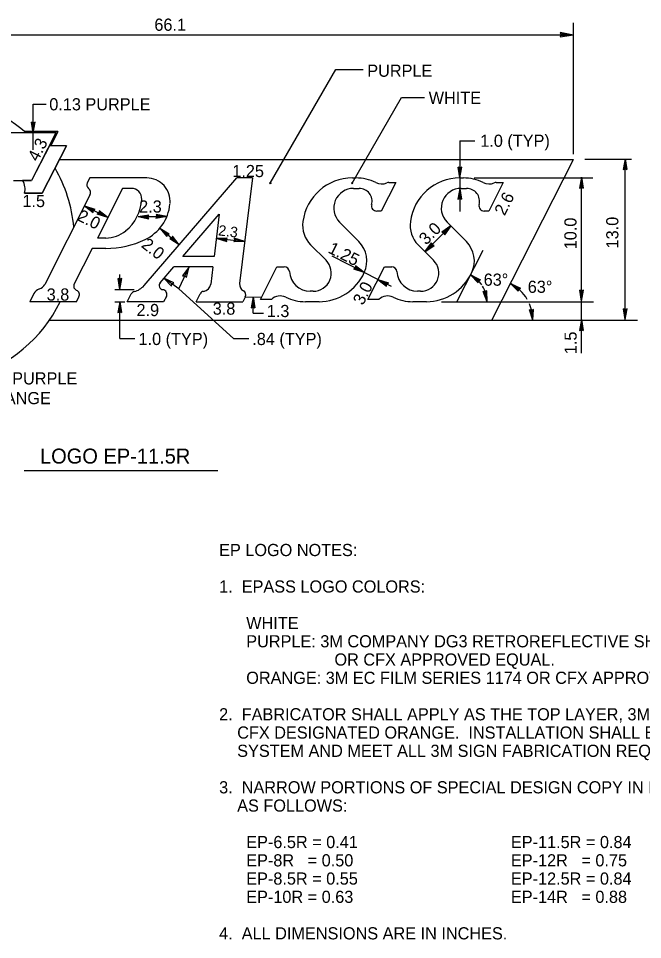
# Model space of a CAD drawing. Extents: x 10268197 to 10269179, y 2141503 to 2142677.
# Drawn here: x 10268671.1 to 10268707, y 2142084.7 to 2142137.7 of the extents above; entities that cross this region are included whole.
import ezdxf

# ---------------------------------------------------------------- set-up
doc = ezdxf.new("R2010")
doc.units = 0
for name, color, linetype in [('1', 7, 'Continuous'), ('20', 7, 'Continuous'), ('21', 7, 'Continuous'), ('3', 7, 'Continuous'), ('52', 7, 'Continuous'), ('Default', 7, 'Continuous'), ('TextNotes', 7, 'Continuous')]:
    doc.layers.add(name, color=color, linetype=linetype)

msp = doc.modelspace()

# ---------------------------------------------------------------- linework, layer by layer
at = {"layer": '1'}
for p, q in [((10268673.238, 2142131.13), (10268664.613, 2142131.13)), ((10268673.362, 2142131.206), (10268671.443, 2142131.206)), ((10268673.238, 2142131.13), (10268671.844, 2142128.396)), ((10268673.362, 2142131.206), (10268672.95, 2142130.4)), ((10268672.865, 2142130.4), (10268671.844, 2142128.396)), ((10268672.456, 2142127.664), (10268673.85, 2142130.4)), ((10268673.85, 2142130.4), (10268672.456, 2142127.664)), ((10268673.85, 2142130.4), (10268672.865, 2142130.4)), ((10268673.85, 2142130.4), (10268672.865, 2142130.4)), ((10268673.447, 2142129.611), (10268703.052, 2142129.611)), ((10268698.337, 2142120.356), (10268703.052, 2142129.611)), ((10268675.19, 2142128.543), (10268675.048, 2142128.262)), ((10268678.475, 2142128.543), (10268675.19, 2142128.543)), ((10268678.316, 2142122.348), (10268683.66, 2142128.543)), ((10268684.559, 2142128.543), (10268683.66, 2142128.543)), ((10268684.559, 2142128.543), (10268683.819, 2142122.472)), ((10268690.317, 2142128.543), (10268690.515, 2142128.543)), ((10268696.504, 2142128.543), (10268696.703, 2142128.543)), ((10268670.804, 2142128.395), (10268671.844, 2142128.396)), ((10268671.844, 2142128.396), (10268671.325, 2142128.396)), ((10268677.076, 2142127.945), (10268675.632, 2142125.089)), ((10268677.586, 2142127.945), (10268677.076, 2142127.945)), ((10268690.38, 2142127.945), (10268690.699, 2142127.945)), ((10268692.806, 2142128.28), (10268691.974, 2142126.635)), ((10268692.414, 2142128.28), (10268692.806, 2142128.28)), ((10268696.567, 2142127.945), (10268696.887, 2142127.945)), ((10268698.994, 2142128.28), (10268698.162, 2142126.635)), ((10268698.601, 2142128.28), (10268698.994, 2142128.28)), ((10268672.456, 2142127.664), (10268671.433, 2142127.665)), ((10268671.433, 2142127.665), (10268672.456, 2142127.664)), ((10268675.199, 2142127.547), (10268672.607, 2142122.422)), ((10268680.553, 2142124.025), (10268682.646, 2142126.451)), ((10268682.646, 2142126.451), (10268682.351, 2142124.025)), ((10268691.974, 2142126.635), (10268691.713, 2142126.635)), ((10268698.162, 2142126.635), (10268697.9, 2142126.635)), ((10268689.573, 2142126.007), (10268690.687, 2142124.885)), ((10268695.761, 2142126.007), (10268696.875, 2142124.885)), ((10268676.12, 2142125.089), (10268675.632, 2142125.089)), ((10268675.329, 2142124.491), (10268674.296, 2142122.446)), ((10268676.12, 2142124.491), (10268675.329, 2142124.491)), ((10268688.796, 2142123.807), (10268687.91, 2142124.701)), ((10268694.984, 2142123.807), (10268694.097, 2142124.701)), ((10268682.351, 2142124.025), (10268680.553, 2142124.025)), ((10268679.245, 2142122.511), (10268680.037, 2142123.428)), ((10268682.278, 2142123.428), (10268680.037, 2142123.428)), ((10268682.278, 2142123.428), (10268682.158, 2142122.436)), ((10268685.018, 2142121.555), (10268685.968, 2142123.436)), ((10268685.968, 2142123.436), (10268686.389, 2142123.436)), ((10268691.206, 2142121.556), (10268692.157, 2142123.436)), ((10268692.157, 2142123.436), (10268692.577, 2142123.435)), ((10268671.97, 2142121.889), (10268671.736, 2142121.423)), ((10268674.428, 2142121.424), (10268674.57, 2142121.706)), ((10268677.353, 2142121.424), (10268677.58, 2142121.875)), ((10268679.601, 2142121.729), (10268679.446, 2142121.423)), ((10268681.317, 2142121.423), (10268681.546, 2142121.874)), ((10268684.147, 2142121.695), (10268684.009, 2142121.423)), ((10268685.654, 2142121.555), (10268685.018, 2142121.555)), ((10268688.053, 2142122.023), (10268687.882, 2142122.023)), ((10268691.841, 2142121.555), (10268691.206, 2142121.556)), ((10268694.241, 2142122.023), (10268694.07, 2142122.023)), ((10268674.428, 2142121.424), (10268671.736, 2142121.423)), ((10268679.446, 2142121.423), (10268677.353, 2142121.424)), ((10268681.317, 2142121.423), (10268684.009, 2142121.423)), ((10268688.392, 2142121.423), (10268687.604, 2142121.424)), ((10268694.579, 2142121.423), (10268693.792, 2142121.424)), ((10268672.864, 2142120.356), (10268698.337, 2142120.356))]:
    msp.add_line(p, q, dxfattribs=at)
for centre, radius, start, end in [((10268666.115, 2142124.99), 8.187, 48.5904, 218.8792), ((10268666.115, 2142124.99), 8.187, 5.051, 30.1953), ((10268678.474, 2142127.197), 1.346, 354.6609, 90), ((10268670.592, 2142127.914), 0.877, 343.4611, 33.2756), ((10268670.592, 2142127.914), 0.877, 343.4611, 33.2756), ((10268677.586, 2142127.347), 0.598, 356.6133, 90), ((10268690.38, 2142126.808), 1.137, 90, 224.7881), ((10268690.699, 2142127.197), 0.748, 345.4379, 90), ((10268696.568, 2142126.808), 1.137, 90, 224.7881), ((10268696.887, 2142127.197), 0.748, 345.4379, 90), ((10268675.645, 2142127.462), 2.542, 309.3947, 356.6133), ((10268677.282, 2142127.297), 2.542, 295.579, 354.2619), ((10268691.713, 2142126.934), 0.299, 165.4379, 270), ((10268697.9, 2142126.934), 0.299, 165.4379, 270), ((10268676.12, 2142126.884), 1.795, 270, 309.3947), ((10268676.12, 2142129.725), 5.235, 270, 295.579), ((10268688.053, 2142123.069), 1.047, 270, 44.7784), ((10268694.241, 2142123.069), 1.047, 270, 44.7784), ((10268686.389, 2142123.136), 0.299, 3.1643, 90), ((10268687.882, 2142123.219), 1.196, 183.1643, 270), ((10268692.576, 2142123.136), 0.299, 3.1643, 90), ((10268694.07, 2142123.219), 1.196, 183.1643, 270), ((10268674.536, 2142122.325), 0.269, 153.1708, 247.5682), ((10268674.33, 2142121.827), 0.269, 333.1431, 67.5682), ((10268679.427, 2142122.355), 0.239, 139.1995, 262.5416), ((10268679.361, 2142121.85), 0.269, 333.166, 82.5416), ((10268681.682, 2142122.494), 0.479, 277.9506, 353.082), ((10268684.235, 2142122.421), 0.419, 173.0593, 241.464), ((10268681.786, 2142121.753), 0.269, 97.9506, 153.1923), ((10268683.906, 2142121.817), 0.269, 333.284, 61.464), ((10268666.115, 2142124.99), 8.187, 237.0648, 334.1734)]:
    msp.add_arc(centre, radius, start, end, dxfattribs=at)
for centre, major_axis, start_param, end_param in [((10268690.316, 2142125.643), (0, 2.9), 0, 1.436562), ((10268690.515, 2142125.907), (0, 2.637), 5.830963, 6.283185), ((10268696.503, 2142125.643), (0, 2.9), 0, 1.436562), ((10268696.702, 2142125.907), (0, 2.637), 5.830963, 6.283185), ((10268675.281, 2142128.142), (0, -0.264), 4.240773, 5.605302), ((10268674.919, 2142127.69), (0, -0.316), 1.099604, 2.46371), ((10268692.001, 2142128.99), (0, 0.791), 2.68937, 3.526171), ((10268692.414, 2142127.963), (0, 0.316), 0, 0.384579), ((10268698.189, 2142128.99), (0, 0.791), 2.68937, 3.526171), ((10268698.601, 2142127.963), (0, 0.316), 0, 0.384579), ((10268689.019, 2142125.819), (0, 1.582), 1.436562, 2.356194), ((10268695.207, 2142125.819), (0, 1.582), 1.436562, 2.356194), ((10268689.577, 2142123.766), (0, -1.582), 1.133591, 2.356194), ((10268695.765, 2142123.766), (0, -1.582), 1.133591, 2.356194), ((10268688.392, 2142124.325), (0, -2.9), 0, 1.133591), ((10268694.579, 2142124.325), (0, -2.9), 0, 1.133591), ((10268672.437, 2142121.65), (0, -0.527), 3.428379, 4.240701), ((10268672.141, 2142122.661), (0, -0.527), 0.286787, 1.099486), ((10268677.526, 2142123.042), (0, -1.055), 0.22194, 0.855152), ((10268677.814, 2142121.755), (0, -0.264), 3.363532, 4.241567), ((10268686.155, 2142121.018), (0, -0.738), 2.69443, 3.895387), ((10268687.604, 2142124.061), (0, -2.637), 5.836023, 6.283185), ((10268692.343, 2142121.018), (0, -0.738), 2.69443, 3.895387), ((10268693.791, 2142124.061), (0, -2.637), 5.836023, 6.283185)]:
    msp.add_ellipse(centre, major_axis=major_axis, ratio=0.992614, start_param=start_param, end_param=end_param, dxfattribs=at)
at = {"layer": '20'}
for p, q in [((10268703.052, 2142130.323), (10268703.052, 2142137.473)), ((10268703.052, 2142136.761), (10268656.015, 2142136.761)), ((10268685.583, 2142128.242), (10268689.354, 2142134.775)), ((10268689.354, 2142134.775), (10268690.943, 2142134.775)), ((10268671.928, 2142131.206), (10268671.927, 2142132.788)), ((10268671.927, 2142132.788), (10268672.677, 2142132.788)), ((10268690.299, 2142128.242), (10268693.141, 2142133.164)), ((10268693.141, 2142133.164), (10268694.46, 2142133.164)), ((10268671.927, 2142130.17), (10268671.928, 2142131.13)), ((10268696.504, 2142130.673), (10268696.504, 2142128.543)), ((10268696.504, 2142130.673), (10268697.362, 2142130.673)), ((10268703.052, 2142129.918), (10268703.052, 2142130.323)), ((10268706.383, 2142129.611), (10268703.691, 2142129.611)), ((10268706.02, 2142120.394), (10268706.021, 2142129.65)), ((10268696.504, 2142128.543), (10268696.504, 2142127.943)), ((10268697.332, 2142128.543), (10268704.156, 2142128.543)), ((10268703.505, 2142121.462), (10268703.505, 2142128.582)), ((10268696.504, 2142127.943), (10268696.503, 2142126.611)), ((10268674.889, 2142126.934), (10268676.223, 2142126.259)), ((10268677.97, 2142126.319), (10268679.629, 2142126.319)), ((10268694.493, 2142124.301), (10268695.986, 2142125.782)), ((10268680.344, 2142124.7), (10268679.229, 2142125.662)), ((10268682.479, 2142125.082), (10268684.112, 2142124.884)), ((10268696.334, 2142121.424), (10268697.843, 2142124.385)), ((10268691, 2142123.096), (10268689.14, 2142124.036)), ((10268680.316, 2142122.159), (10268680.913, 2142123.436)), ((10268676.924, 2142122.136), (10268676.924, 2142122.994)), ((10268680.316, 2142122.159), (10268679.447, 2142122.776)), ((10268691.785, 2142122.699), (10268691, 2142123.096)), ((10268692.569, 2142122.302), (10268691.784, 2142122.699)), ((10268676.642, 2142122.136), (10268677.74, 2142122.136)), ((10268683.473, 2142119.313), (10268680.316, 2142122.159)), ((10268684.147, 2142121.695), (10268685.089, 2142121.696)), ((10268684.603, 2142120.767), (10268684.603, 2142121.696)), ((10268676.642, 2142121.424), (10268677.206, 2142121.424)), ((10268676.924, 2142119.313), (10268676.924, 2142121.424)), ((10268695.451, 2142121.424), (10268698.881, 2142121.424)), ((10268698.881, 2142121.424), (10268704.195, 2142121.424)), ((10268703.505, 2142120.395), (10268703.505, 2142121.462)), ((10268684.603, 2142120.767), (10268685.186, 2142120.766)), ((10268698.337, 2142120.356), (10268706.724, 2142120.356)), ((10268703.505, 2142118.468), (10268703.505, 2142120.395)), ((10268676.924, 2142119.313), (10268677.796, 2142119.313)), ((10268683.473, 2142119.313), (10268684.345, 2142119.313))]:
    msp.add_line(p, q, dxfattribs=at)
for centre in [(10268685.583, 2142128.242), (10268690.299, 2142128.242)]:
    msp.add_circle(centre, 0.0356, dxfattribs=at)
for centre, radius, start, end in [((10268696.334, 2142121.424), 1.73, 33.9529, 63.0014), ((10268696.334, 2142121.424), 1.73, 0, 31.4593), ((10268698.337, 2142120.356), 2.37, 30.3328, 63.0012), ((10268698.337, 2142120.356), 2.37, 360, 23.4794)]:
    msp.add_arc(centre, radius, start, end, dxfattribs=at)
at = {"layer": '21'}
for p, q in [((10268703.052, 2142136.761), (10268702.278, 2142136.912)), ((10268702.278, 2142136.912), (10268702.335, 2142136.774)), ((10268702.335, 2142136.774), (10268702.273, 2142136.638)), ((10268703.052, 2142136.761), (10268702.273, 2142136.638)), ((10268703.052, 2142136.761), (10268702.306, 2142136.709)), ((10268703.052, 2142136.761), (10268702.308, 2142136.839)), ((10268671.928, 2142131.13), (10268671.829, 2142131.754)), ((10268671.937, 2142131.704), (10268671.829, 2142131.754)), ((10268671.928, 2142131.13), (10268671.886, 2142131.727)), ((10268671.928, 2142131.13), (10268672.048, 2142131.75)), ((10268671.928, 2142131.13), (10268671.99, 2142131.726)), ((10268672.048, 2142131.75), (10268671.937, 2142131.704)), ((10268706.021, 2142129.65), (10268705.9, 2142129.03)), ((10268706.021, 2142129.65), (10268705.958, 2142129.054)), ((10268706.021, 2142129.65), (10268706.12, 2142129.026)), ((10268706.021, 2142129.65), (10268706.062, 2142129.052)), ((10268696.504, 2142128.543), (10268696.405, 2142129.167)), ((10268696.513, 2142129.118), (10268696.405, 2142129.167)), ((10268696.504, 2142128.543), (10268696.462, 2142129.141)), ((10268696.504, 2142128.543), (10268696.624, 2142129.163)), ((10268696.504, 2142128.543), (10268696.566, 2142129.139)), ((10268696.624, 2142129.163), (10268696.513, 2142129.118)), ((10268705.9, 2142129.03), (10268706.011, 2142129.075)), ((10268706.011, 2142129.075), (10268706.12, 2142129.026)), ((10268703.505, 2142128.582), (10268703.385, 2142127.962)), ((10268703.505, 2142128.582), (10268703.443, 2142127.986)), ((10268703.505, 2142128.582), (10268703.604, 2142127.958)), ((10268703.505, 2142128.582), (10268703.547, 2142127.985)), ((10268696.504, 2142127.943), (10268696.383, 2142127.323)), ((10268696.504, 2142127.943), (10268696.441, 2142127.347)), ((10268696.504, 2142127.943), (10268696.602, 2142127.32)), ((10268696.504, 2142127.943), (10268696.545, 2142127.346)), ((10268703.385, 2142127.962), (10268703.495, 2142128.007)), ((10268703.495, 2142128.007), (10268703.604, 2142127.958)), ((10268696.383, 2142127.323), (10268696.494, 2142127.369)), ((10268696.494, 2142127.369), (10268696.602, 2142127.32)), ((10268674.889, 2142126.934), (10268675.49, 2142126.741)), ((10268674.889, 2142126.934), (10268675.388, 2142126.547)), ((10268674.889, 2142126.934), (10268675.393, 2142126.61)), ((10268674.889, 2142126.934), (10268675.441, 2142126.702)), ((10268675.388, 2142126.547), (10268675.397, 2142126.666)), ((10268675.397, 2142126.666), (10268675.49, 2142126.741)), ((10268675.715, 2142126.527), (10268675.622, 2142126.452)), ((10268676.223, 2142126.259), (10268675.622, 2142126.452)), ((10268676.223, 2142126.259), (10268675.672, 2142126.491)), ((10268675.725, 2142126.646), (10268675.715, 2142126.527)), ((10268676.223, 2142126.259), (10268675.72, 2142126.583)), ((10268676.223, 2142126.259), (10268675.725, 2142126.646)), ((10268677.97, 2142126.319), (10268678.594, 2142126.418)), ((10268677.97, 2142126.319), (10268678.567, 2142126.361)), ((10268677.97, 2142126.319), (10268678.59, 2142126.199)), ((10268677.97, 2142126.319), (10268678.566, 2142126.257)), ((10268678.544, 2142126.309), (10268678.594, 2142126.418)), ((10268678.59, 2142126.199), (10268678.544, 2142126.309)), ((10268679.055, 2142126.329), (10268679.005, 2142126.22)), ((10268679.629, 2142126.319), (10268679.005, 2142126.22)), ((10268679.629, 2142126.319), (10268679.009, 2142126.439)), ((10268679.009, 2142126.439), (10268679.055, 2142126.329)), ((10268679.629, 2142126.319), (10268679.031, 2142126.277)), ((10268679.629, 2142126.319), (10268679.033, 2142126.381)), ((10268695.986, 2142125.782), (10268695.461, 2142125.431)), ((10268695.986, 2142125.782), (10268695.518, 2142125.406)), ((10268695.986, 2142125.782), (10268695.591, 2142125.332)), ((10268695.986, 2142125.782), (10268695.612, 2142125.272)), ((10268679.229, 2142125.662), (10268679.766, 2142125.329)), ((10268679.229, 2142125.662), (10268679.62, 2142125.166)), ((10268679.229, 2142125.662), (10268679.64, 2142125.226)), ((10268679.229, 2142125.662), (10268679.709, 2142125.303)), ((10268679.62, 2142125.166), (10268679.658, 2142125.279)), ((10268679.658, 2142125.279), (10268679.766, 2142125.329)), ((10268695.461, 2142125.431), (10268695.571, 2142125.385)), ((10268695.571, 2142125.385), (10268695.612, 2142125.272)), ((10268679.916, 2142125.083), (10268679.807, 2142125.032)), ((10268680.344, 2142124.7), (10268679.807, 2142125.032)), ((10268680.344, 2142124.7), (10268679.865, 2142125.058)), ((10268679.953, 2142125.196), (10268679.916, 2142125.083)), ((10268680.344, 2142124.7), (10268679.934, 2142125.136)), ((10268680.344, 2142124.7), (10268679.953, 2142125.196)), ((10268682.479, 2142125.082), (10268683.111, 2142125.105)), ((10268682.479, 2142125.082), (10268683.08, 2142124.888)), ((10268682.479, 2142125.082), (10268683.063, 2142124.948)), ((10268682.479, 2142125.082), (10268683.077, 2142125.052)), ((10268683.048, 2142125.003), (10268683.111, 2142125.105)), ((10268683.08, 2142124.888), (10268683.048, 2142125.003)), ((10268683.543, 2142124.963), (10268683.481, 2142124.861)), ((10268684.112, 2142124.884), (10268683.481, 2142124.861)), ((10268684.112, 2142124.884), (10268683.511, 2142125.078)), ((10268683.511, 2142125.078), (10268683.543, 2142124.963)), ((10268684.112, 2142124.884), (10268683.514, 2142124.914)), ((10268684.112, 2142124.884), (10268683.528, 2142125.017)), ((10268694.493, 2142124.301), (10268694.866, 2142124.811)), ((10268694.493, 2142124.301), (10268694.887, 2142124.751)), ((10268694.907, 2142124.699), (10268694.866, 2142124.811)), ((10268694.493, 2142124.301), (10268694.96, 2142124.677)), ((10268694.493, 2142124.301), (10268695.018, 2142124.652)), ((10268695.018, 2142124.652), (10268694.907, 2142124.699)), ((10268690.491, 2142123.364), (10268690.398, 2142123.289)), ((10268691, 2142123.096), (10268690.398, 2142123.289)), ((10268691, 2142123.096), (10268690.447, 2142123.328)), ((10268690.5, 2142123.483), (10268690.491, 2142123.364)), ((10268691, 2142123.096), (10268690.496, 2142123.421)), ((10268691, 2142123.096), (10268690.5, 2142123.483)), ((10268676.924, 2142122.136), (10268676.825, 2142122.759)), ((10268676.934, 2142122.71), (10268676.825, 2142122.759)), ((10268676.924, 2142122.136), (10268676.882, 2142122.733)), ((10268676.924, 2142122.136), (10268677.044, 2142122.755)), ((10268676.924, 2142122.136), (10268676.986, 2142122.732)), ((10268677.044, 2142122.755), (10268676.934, 2142122.71)), ((10268691.784, 2142122.699), (10268692.386, 2142122.506)), ((10268691.784, 2142122.699), (10268692.283, 2142122.312)), ((10268691.784, 2142122.699), (10268692.288, 2142122.375)), ((10268691.784, 2142122.699), (10268692.336, 2142122.467)), ((10268697.12, 2142122.966), (10268697.682, 2142122.678)), ((10268697.12, 2142122.966), (10268697.549, 2142122.503)), ((10268697.12, 2142122.966), (10268697.564, 2142122.564)), ((10268697.12, 2142122.966), (10268697.626, 2142122.647)), ((10268697.549, 2142122.503), (10268697.577, 2142122.619)), ((10268697.577, 2142122.619), (10268697.682, 2142122.678)), ((10268692.283, 2142122.312), (10268692.293, 2142122.431)), ((10268692.293, 2142122.431), (10268692.386, 2142122.506)), ((10268698.063, 2142122.057), (10268697.963, 2142121.991)), ((10268698.065, 2142121.426), (10268698.063, 2142122.057)), ((10268699.414, 2142122.469), (10268699.989, 2142122.207)), ((10268699.414, 2142122.469), (10268699.864, 2142122.026)), ((10268699.414, 2142122.469), (10268699.876, 2142122.087)), ((10268699.414, 2142122.469), (10268699.935, 2142122.173)), ((10268699.864, 2142122.026), (10268699.887, 2142122.143)), ((10268699.887, 2142122.143), (10268699.989, 2142122.207)), ((10268703.505, 2142121.462), (10268703.406, 2142122.086)), ((10268703.515, 2142122.036), (10268703.406, 2142122.086)), ((10268703.505, 2142121.462), (10268703.463, 2142122.059)), ((10268703.505, 2142121.462), (10268703.625, 2142122.082)), ((10268703.505, 2142121.462), (10268703.568, 2142122.058)), ((10268703.625, 2142122.082), (10268703.515, 2142122.036)), ((10268684.603, 2142121.696), (10268684.482, 2142121.076)), ((10268684.603, 2142121.696), (10268684.54, 2142121.1)), ((10268684.603, 2142121.696), (10268684.702, 2142121.072)), ((10268684.603, 2142121.696), (10268684.645, 2142121.098)), ((10268698.065, 2142121.426), (10268697.847, 2142122.018)), ((10268697.963, 2142121.991), (10268697.847, 2142122.018)), ((10268698.065, 2142121.426), (10268697.908, 2142122.004)), ((10268698.065, 2142121.426), (10268698.01, 2142122.023)), ((10268676.924, 2142121.424), (10268676.804, 2142120.804)), ((10268676.924, 2142121.424), (10268676.862, 2142120.828)), ((10268676.924, 2142121.424), (10268677.023, 2142120.8)), ((10268676.924, 2142121.424), (10268676.966, 2142120.826)), ((10268684.482, 2142121.076), (10268684.593, 2142121.121)), ((10268684.593, 2142121.121), (10268684.702, 2142121.072)), ((10268706.02, 2142120.394), (10268705.921, 2142121.018)), ((10268706.03, 2142120.969), (10268705.921, 2142121.018)), ((10268706.02, 2142120.394), (10268706.141, 2142121.014)), ((10268706.141, 2142121.014), (10268706.03, 2142120.969)), ((10268676.804, 2142120.804), (10268676.914, 2142120.85)), ((10268676.914, 2142120.85), (10268677.023, 2142120.8)), ((10268700.71, 2142120.353), (10268700.514, 2142120.954)), ((10268700.63, 2142120.922), (10268700.514, 2142120.954)), ((10268700.71, 2142120.353), (10268700.575, 2142120.937)), ((10268700.732, 2142120.984), (10268700.63, 2142120.922)), ((10268700.71, 2142120.353), (10268700.678, 2142120.952)), ((10268700.71, 2142120.353), (10268700.732, 2142120.984)), ((10268706.02, 2142120.394), (10268705.978, 2142120.992)), ((10268706.02, 2142120.394), (10268706.082, 2142120.99)), ((10268703.505, 2142120.395), (10268703.385, 2142119.775)), ((10268703.505, 2142120.395), (10268703.443, 2142119.799)), ((10268703.505, 2142120.395), (10268703.604, 2142119.771)), ((10268703.505, 2142120.395), (10268703.547, 2142119.797)), ((10268703.385, 2142119.775), (10268703.495, 2142119.821)), ((10268703.495, 2142119.821), (10268703.604, 2142119.771))]:
    msp.add_line(p, q, dxfattribs=at)
at = {"layer": '3'}
msp.add_lwpolyline([(10268671.443, 2142131.206), (10268673.362, 2142131.206), (10268672.95, 2142130.4), (10268672.865, 2142130.4), (10268673.238, 2142131.13), (10268671.531, 2142131.131)], close=True, dxfattribs=at)
at = {"layer": '52'}
for p, q in [((10268680.913, 2142123.436), (10268680.535, 2142122.916)), ((10268680.752, 2142122.814), (10268680.913, 2142123.436)), ((10268679.447, 2142122.776), (10268679.892, 2142122.311)), ((10268680.03, 2142122.507), (10268679.447, 2142122.776)), ((10268680.535, 2142122.916), (10268680.666, 2142122.907)), ((10268680.666, 2142122.907), (10268680.752, 2142122.814)), ((10268679.892, 2142122.311), (10268679.923, 2142122.438)), ((10268679.923, 2142122.438), (10268680.03, 2142122.507))]:
    msp.add_line(p, q, dxfattribs=at)
at = {"layer": 'Default'}
msp.add_line((10268671.411, 2142111.721), (10268682.559, 2142111.721), dxfattribs=at)

# ---------------------------------------------------------------- texts
at = {"layer": '1'}
msp.add_text('LOGO EP-11.5R', height=0.8624, dxfattribs=at).set_placement((10268672.327, 2142112.113))
at = {"layer": '20'}
for s, p in [('66.1', (10268678.911, 2142137.01)), ('PURPLE', (10268691.17, 2142134.363)), ('WHITE', (10268694.706, 2142132.804)), ('0.13 PURPLE', (10268672.861, 2142132.431)), ('1.0 (TYP)', (10268697.676, 2142130.334)), ('1.25', (10268683.399, 2142128.59)), ('1.5', (10268671.314, 2142126.867)), ('2.3', (10268678.035, 2142126.551)), ('63°', (10268697.872, 2142122.344)), ('63°', (10268700.41, 2142121.934)), ('3.8', (10268672.71, 2142121.489)), ('2.9', (10268677.882, 2142120.595)), ('3.8', (10268682.272, 2142120.678)), ('1.3', (10268685.384, 2142120.54)), ('1.0 (TYP)', (10268678, 2142118.932)), ('.84 (TYP)', (10268684.549, 2142118.932)), ('PURPLE', (10268670.725, 2142116.663)), ('ORANGE', (10268668.895, 2142115.53))]:
    msp.add_text(s, height=0.7, dxfattribs=at).set_placement(p)
for s, height, rotation, p in [('4.3', 0.7, 63.001, (10268672.201, 2142129.442)), ('2.6', 0.7, 63.1678, (10268699.074, 2142126.33)), ('2.0', 0.7, 333.1665, (10268674.413, 2142126.138)), ('2.3', 0.6037, 353.0765, (10268682.565, 2142125.244)), ('3.0', 0.7, 44.7737, (10268694.56, 2142124.647)), ('10.0', 0.7, 90, (10268703.217, 2142124.439)), ('13.0', 0.7, 90, (10268705.628, 2142124.489)), ('2.0', 0.7, 321.8741, (10268678.112, 2142124.602)), ('1.25', 0.7, 333.1861, (10268688.86, 2142124.274)), ('3.0', 0.7, 63.1839, (10268690.926, 2142121.179)), ('1.5', 0.7, 90, (10268703.226, 2142118.405))]:
    msp.add_text(s, height=height, rotation=rotation, dxfattribs=at).set_placement(p)
at = {"layer": 'TextNotes'}
for s, p in [('EP LOGO NOTES:', (10268682.64, 2142106.792)), ('1.  EPASS LOGO COLORS:', (10268682.64, 2142104.692)), ('      WHITE', (10268682.64, 2142102.592)), ('      PURPLE: 3M COMPANY DG3 RETROREFLECTIVE SHEETING MATCHING 3M 4058FL ', (10268682.64, 2142101.542)), ('    OR CFX APPROVED EQUAL.', (10268688.24, 2142100.492)), ('      ORANGE: 3M EC FILM SERIES 1174 OR CFX APPROVED EQUAL.', (10268682.64, 2142099.442)), ('2.  FABRICATOR SHALL APPLY AS THE TOP LAYER, 3M COMPANY EC FILM 1170 CLEAR ON', (10268682.64, 2142097.342)), ('    CFX DESIGNATED ORANGE.  INSTALLATION SHALL BE PART OF A 3M MATCHED COMPONENT', (10268682.64, 2142096.292)), ('    SYSTEM AND MEET ALL 3M SIGN FABRICATION REQUIREMENTS.  CONTACT 3M AT 1-800-553-1380.', (10268682.64, 2142095.242)), ('3.  NARROW PORTIONS OF SPECIAL DESIGN COPY IN EPASS LOGOS SHALL HAVE MINIMUM THICKNESS', (10268682.64, 2142093.142)), ('    AS FOLLOWS:', (10268682.64, 2142092.092)), ('      EP-6.5R = 0.41', (10268682.64, 2142089.992)), ('EP-11.5R = 0.84', (10268699.44, 2142089.992)), ('      EP-8R   = 0.50', (10268682.64, 2142088.942)), ('EP-12R   = 0.75', (10268699.44, 2142088.942)), ('      EP-8.5R = 0.55', (10268682.64, 2142087.892)), ('EP-12.5R = 0.84', (10268699.44, 2142087.892)), ('      EP-10R = 0.63', (10268682.64, 2142086.842)), ('EP-14R   = 0.88', (10268699.44, 2142086.842)), ('4.  ALL DIMENSIONS ARE IN INCHES.', (10268682.64, 2142084.742))]:
    msp.add_text(s, height=0.7, dxfattribs=at).set_placement(p)

doc.saveas('drawing.dxf')
